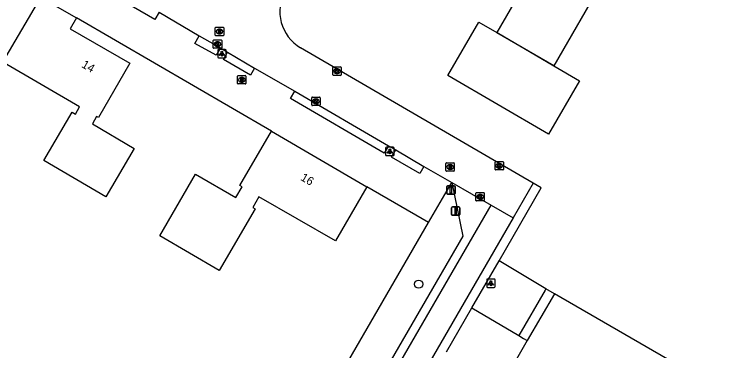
# Model space of a CAD drawing. Extents: x 156502 to 159074, y 384229 to 386094.
# Drawn here: x 157152.4 to 157237.7, y 385787.5 to 385827.5 of the extents above; entities that cross this region are included whole.
import ezdxf

# ---------------------------------------------------------------- set-up
doc = ezdxf.new("R2010")
doc.units = 0
for name, color, linetype in [('IMGEO_Afsluitpaal', 7, 'Continuous'), ('IMGEO_Berm_groen', 7, 'Continuous'), ('IMGEO_Boom', 7, 'Continuous'), ('IMGEO_Grasland_overig', 7, 'Continuous'), ('IMGEO_Groenvoorziening', 7, 'Continuous'), ('IMGEO_Hek', 7, 'Continuous'), ('IMGEO_Kolk', 7, 'Continuous'), ('IMGEO_Lichtpunt', 7, 'Continuous'), ('IMGEO_Pand', 7, 'Continuous'), ('IMGEO_Pand_nummerreeks', 7, 'Continuous'), ('IMGEO_Pand_vergunning_verleend', 7, 'Continuous'), ('IMGEO_Rijbaan_lokaal_gesloten', 7, 'Continuous'), ('IMGEO_Rijbaan_lokaal_halfverhard', 7, 'Continuous'), ('IMGEO_Rijbaan_lokaal_open', 7, 'Continuous'), ('IMGEO_Rioolput', 7, 'Continuous'), ('IMGEO_Voetpad_open', 7, 'Continuous')]:
    doc.layers.add(name, color=color, linetype=linetype)

msp = doc.modelspace()

# ---------------------------------------------------------------- linework, layer by layer
at = {"layer": 'IMGEO_Afsluitpaal'}
for p, q in [((157203.9, 385806.17), (157203.9, 385806.97)), ((157203.9, 385806.97), (157203.9, 385806.17)), ((157204, 385807.07), (157204.79, 385807.07)), ((157204.79, 385807.07), (157204, 385807.07)), ((157204.89, 385806.97), (157204.89, 385806.17)), ((157204.89, 385806.17), (157204.89, 385806.97)), ((157204.79, 385806.07), (157204, 385806.07)), ((157204, 385806.07), (157204.79, 385806.07)), ((157204.466, 385803.659), (157204.466, 385804.459)), ((157204.466, 385804.459), (157204.466, 385803.659)), ((157204.566, 385804.559), (157205.356, 385804.559)), ((157205.356, 385804.559), (157204.566, 385804.559)), ((157205.456, 385804.459), (157205.456, 385803.659)), ((157205.456, 385803.659), (157205.456, 385804.459)), ((157205.356, 385803.559), (157204.566, 385803.559)), ((157204.566, 385803.559), (157205.356, 385803.559))]:
    msp.add_line(p, q, dxfattribs=at)
for points in [[(157204.32, 385806.945), (157204.47, 385806.945), (157204.47, 385806.195), (157204.32, 385806.195), (157204.32, 385806.945)], [(157204.886, 385804.434), (157205.036, 385804.434), (157205.036, 385803.684), (157204.886, 385803.684), (157204.886, 385804.434)]]:
    msp.add_lwpolyline(points, dxfattribs=at)
for centre, start, end in [((157204, 385806.97), 90, 180), ((157204, 385806.97), 90, 180), ((157204.79, 385806.97), 0, 90), ((157204.79, 385806.97), 360, 90), ((157204, 385806.17), 180, 270), ((157204, 385806.17), 180, 270), ((157204.79, 385806.17), 270, 0), ((157204.79, 385806.17), 270, 0), ((157204.566, 385804.459), 90, 180), ((157204.566, 385804.459), 90, 180), ((157205.356, 385804.459), 0, 90), ((157205.356, 385804.459), 360, 90), ((157204.566, 385803.659), 180, 270), ((157204.566, 385803.659), 180, 270), ((157205.356, 385803.659), 270, 0), ((157205.356, 385803.659), 270, 0)]:
    msp.add_arc(centre, 0.1, start, end, dxfattribs=at)
at = {"layer": 'IMGEO_Berm_groen'}
msp.add_lwpolyline([(157149.855, 385730.69), (157157.489, 385726.3), (157201.732, 385802.693)], dxfattribs=at)
at = {"layer": 'IMGEO_Boom'}
msp.add_circle((157200.566, 385795.368), 0.489, dxfattribs=at)
at = {"layer": 'IMGEO_Grasland_overig'}
for points in [[(157215.692, 385794.809), (157210.12, 385798.131)], [(157216.71, 385794.202), (157215.692, 385794.809)], [(157246.925, 385776.791), (157216.71, 385794.202)]]:
    msp.add_lwpolyline(points, dxfattribs=at)
at = {"layer": 'IMGEO_Groenvoorziening'}
for points in [[(157215.692, 385794.809), (157215.606, 385794.649), (157212.477, 385789.254)], [(157216.71, 385794.202), (157213.481, 385788.661)]]:
    msp.add_lwpolyline(points, dxfattribs=at)
at = {"layer": 'IMGEO_Hek'}
for points in [[(157183.031, 385813.57), (157159.85, 385827.054)], [(157201.732, 385802.693), (157194.383, 385806.952)], [(157149.855, 385730.69), (157157.489, 385726.3), (157201.732, 385802.693)]]:
    msp.add_lwpolyline(points, dxfattribs=at)
at = {"layer": 'IMGEO_Kolk'}
for p, q in [((157176.113, 385823.494), (157176.113, 385824.346)), ((157176.188, 385824.42), (157177.04, 385824.42)), ((157177.114, 385824.346), (157177.114, 385823.494)), ((157176.624, 385823.64), (157176.599, 385823.64)), ((157176.601, 385824.2), (157176.626, 385824.2)), ((157177.04, 385823.42), (157176.188, 385823.42)), ((157190.341, 385820.279), (157190.341, 385821.131)), ((157190.416, 385821.205), (157191.268, 385821.205)), ((157190.829, 385820.985), (157190.854, 385820.985)), ((157191.342, 385821.131), (157191.342, 385820.279)), ((157191.268, 385820.205), (157190.416, 385820.205)), ((157190.852, 385820.425), (157190.827, 385820.425)), ((157187.831, 385816.688), (157187.831, 385817.54)), ((157187.906, 385817.614), (157188.758, 385817.614)), ((157188.832, 385817.54), (157188.832, 385816.688)), ((157188.342, 385816.834), (157188.317, 385816.834)), ((157188.319, 385817.394), (157188.344, 385817.394)), ((157188.758, 385816.614), (157187.906, 385816.614)), ((157209.647, 385809.023), (157209.647, 385809.875)), ((157209.722, 385809.949), (157210.574, 385809.949)), ((157210.648, 385809.875), (157210.648, 385809.023)), ((157210.158, 385809.169), (157210.133, 385809.169)), ((157210.135, 385809.729), (157210.16, 385809.729)), ((157210.574, 385808.949), (157209.722, 385808.949)), ((157207.37, 385805.338), (157207.37, 385806.19)), ((157207.445, 385806.264), (157208.297, 385806.264)), ((157207.858, 385806.044), (157207.883, 385806.044)), ((157208.371, 385806.19), (157208.371, 385805.338)), ((157208.297, 385805.264), (157207.445, 385805.264)), ((157207.881, 385805.484), (157207.856, 385805.484))]:
    msp.add_line(p, q, dxfattribs=at)
for points in [[(157176.113, 385823.494), (157176.113, 385824.346)], [(157176.188, 385824.42), (157177.04, 385824.42)], [(157177.114, 385824.346), (157177.114, 385823.494)], [(157176.434, 385824.12), (157176.557, 385824.12), (157176.557, 385823.969), (157176.687, 385824.12), (157176.851, 385824.12), (157176.705, 385823.969), (157176.858, 385823.72), (157176.706, 385823.72), (157176.621, 385823.884), (157176.557, 385823.817), (157176.557, 385823.72), (157176.434, 385823.72), (157176.434, 385824.12)], [(157177.04, 385823.42), (157176.188, 385823.42)], [(157190.341, 385820.279), (157190.341, 385821.131)], [(157190.416, 385821.205), (157191.268, 385821.205)], [(157190.662, 385820.905), (157190.785, 385820.905), (157190.785, 385820.754), (157190.915, 385820.905), (157191.079, 385820.905), (157190.933, 385820.754), (157191.086, 385820.505), (157190.934, 385820.505), (157190.849, 385820.669), (157190.785, 385820.602), (157190.785, 385820.505), (157190.662, 385820.505), (157190.662, 385820.905)], [(157191.342, 385821.131), (157191.342, 385820.279)], [(157191.268, 385820.205), (157190.416, 385820.205)], [(157187.831, 385816.688), (157187.831, 385817.54)], [(157187.906, 385817.614), (157188.758, 385817.614)], [(157188.832, 385817.54), (157188.832, 385816.688)], [(157188.152, 385817.314), (157188.275, 385817.314), (157188.275, 385817.163), (157188.405, 385817.314), (157188.569, 385817.314), (157188.423, 385817.163), (157188.576, 385816.914), (157188.424, 385816.914), (157188.339, 385817.078), (157188.275, 385817.011), (157188.275, 385816.914), (157188.152, 385816.914), (157188.152, 385817.314)], [(157188.758, 385816.614), (157187.906, 385816.614)], [(157209.647, 385809.023), (157209.647, 385809.875)], [(157209.722, 385809.949), (157210.574, 385809.949)], [(157210.648, 385809.875), (157210.648, 385809.023)], [(157209.968, 385809.649), (157210.091, 385809.649), (157210.091, 385809.498), (157210.221, 385809.649), (157210.385, 385809.649), (157210.239, 385809.498), (157210.392, 385809.249), (157210.24, 385809.249), (157210.155, 385809.413), (157210.091, 385809.346), (157210.091, 385809.249), (157209.968, 385809.249), (157209.968, 385809.649)], [(157210.574, 385808.949), (157209.722, 385808.949)], [(157207.37, 385805.338), (157207.37, 385806.19)], [(157207.445, 385806.264), (157208.297, 385806.264)], [(157207.691, 385805.964), (157207.814, 385805.964), (157207.814, 385805.813), (157207.944, 385805.964), (157208.108, 385805.964), (157207.962, 385805.813), (157208.115, 385805.564), (157207.963, 385805.564), (157207.878, 385805.728), (157207.814, 385805.661), (157207.814, 385805.564), (157207.691, 385805.564), (157207.691, 385805.964)], [(157208.371, 385806.19), (157208.371, 385805.338)], [(157208.297, 385805.264), (157207.445, 385805.264)]]:
    msp.add_lwpolyline(points, dxfattribs=at)
for centre, start, end in [((157176.19, 385824.344), 91.55205, 178.44795), ((157176.19, 385824.344), 91.55205, 178.44795), ((157177.038, 385824.344), 1.55205, 88.44795), ((157177.038, 385824.344), 1.55205, 88.44795), ((157176.19, 385823.496), 181.55205, 268.44795), ((157176.19, 385823.496), 181.55205, 268.44795), ((157177.038, 385823.496), 271.55205, 358.44795), ((157177.038, 385823.496), 271.55205, 358.44795), ((157190.418, 385821.129), 91.55205, 178.44795), ((157190.418, 385821.129), 91.55205, 178.44795), ((157191.266, 385821.129), 1.55205, 88.44795), ((157191.266, 385821.129), 1.55205, 88.44795), ((157190.418, 385820.281), 181.55205, 268.44795), ((157190.418, 385820.281), 181.55205, 268.44795), ((157191.266, 385820.281), 271.55205, 358.44795), ((157191.266, 385820.281), 271.55205, 358.44795), ((157187.908, 385817.538), 91.55205, 178.44795), ((157187.908, 385817.538), 91.55205, 178.44795), ((157188.756, 385817.538), 1.55205, 88.44795), ((157188.756, 385817.538), 1.55205, 88.44795), ((157187.908, 385816.69), 181.55205, 268.44795), ((157187.908, 385816.69), 181.55205, 268.44795), ((157188.756, 385816.69), 271.55205, 358.44795), ((157188.756, 385816.69), 271.55205, 358.44795), ((157209.724, 385809.873), 91.55205, 178.44795), ((157209.724, 385809.873), 91.55205, 178.44795), ((157210.572, 385809.873), 1.55205, 88.44795), ((157210.572, 385809.873), 1.55205, 88.44795), ((157209.724, 385809.025), 181.55205, 268.44795), ((157209.724, 385809.025), 181.55205, 268.44795), ((157210.572, 385809.025), 271.55205, 358.44795), ((157210.572, 385809.025), 271.55205, 358.44795), ((157207.447, 385806.188), 91.55205, 178.44795), ((157207.447, 385806.188), 91.55205, 178.44795), ((157208.295, 385806.188), 1.55205, 88.44795), ((157208.295, 385806.188), 1.55205, 88.44795), ((157207.447, 385805.34), 181.55205, 268.44795), ((157207.447, 385805.34), 181.55205, 268.44795), ((157208.295, 385805.34), 271.55205, 358.44795), ((157208.295, 385805.34), 271.55205, 358.44795)]:
    msp.add_arc(centre, 0.0765, start, end, dxfattribs=at)
for centre, major_axis, ratio, start_param, end_param in [((157176.6, 385823.92), (-0.387, 0.002), 0.722429, 4.712389, 7.853982), ((157176.625, 385823.92), (-0.39, 0.002), 0.717154, 1.570796, 4.712389), ((157190.828, 385820.705), (-0.387, 0.002), 0.722429, 4.712389, 7.853982), ((157190.853, 385820.705), (-0.39, 0.002), 0.717154, 1.570796, 4.712389), ((157188.318, 385817.114), (-0.387, 0.002), 0.722429, 4.712389, 7.853982), ((157188.343, 385817.114), (-0.39, 0.002), 0.717154, 1.570796, 4.712389), ((157210.134, 385809.449), (-0.387, 0.002), 0.722429, 4.712389, 7.853982), ((157210.159, 385809.449), (-0.39, 0.002), 0.717154, 1.570796, 4.712389), ((157207.857, 385805.764), (-0.387, 0.002), 0.722429, 4.712389, 7.853982), ((157207.882, 385805.764), (-0.39, 0.002), 0.717154, 1.570796, 4.712389)]:
    msp.add_ellipse(centre, major_axis=major_axis, ratio=ratio, start_param=start_param, end_param=end_param, dxfattribs=at)
at = {"layer": 'IMGEO_Lichtpunt'}
for p, q in [((157176.644, 385823.182), (157176.644, 385822.375)), ((157176.644, 385823.182), (157176.644, 385822.375)), ((157177.546, 385823.277), (157176.738, 385823.277)), ((157177.546, 385823.277), (157176.738, 385823.277)), ((157177.64, 385822.375), (157177.64, 385823.182)), ((157177.64, 385822.375), (157177.64, 385823.182)), ((157176.738, 385822.281), (157177.546, 385822.281)), ((157176.738, 385822.281), (157177.546, 385822.281)), ((157196.63, 385811.564), (157196.63, 385810.757)), ((157196.63, 385811.564), (157196.63, 385810.757)), ((157197.532, 385811.659), (157196.724, 385811.659)), ((157197.532, 385811.659), (157196.724, 385811.659)), ((157197.626, 385810.757), (157197.626, 385811.564)), ((157197.626, 385810.757), (157197.626, 385811.564)), ((157196.724, 385810.663), (157197.532, 385810.663)), ((157196.724, 385810.663), (157197.532, 385810.663)), ((157208.654, 385795.885), (157208.654, 385795.078)), ((157208.654, 385795.885), (157208.654, 385795.078)), ((157209.556, 385795.98), (157208.748, 385795.98)), ((157209.556, 385795.98), (157208.748, 385795.98)), ((157209.65, 385795.078), (157209.65, 385795.885)), ((157209.65, 385795.078), (157209.65, 385795.885)), ((157208.748, 385794.984), (157209.556, 385794.984)), ((157208.748, 385794.984), (157209.556, 385794.984))]:
    msp.add_line(p, q, dxfattribs=at)
for points in [[(157177.018, 385822.846), (157177.057, 385822.818), (157176.869, 385822.556), (157176.831, 385822.583), (157177.018, 385822.846)], [(157177.12, 385822.798), (157177.167, 385822.798), (157177.167, 385822.476), (157177.12, 385822.476), (157177.12, 385822.798)], [(157177.23, 385822.818), (157177.268, 385822.845), (157177.455, 385822.583), (157177.416, 385822.555), (157177.23, 385822.818)], [(157197.004, 385811.228), (157197.043, 385811.2), (157196.855, 385810.938), (157196.817, 385810.965), (157197.004, 385811.228)], [(157197.106, 385811.18), (157197.153, 385811.18), (157197.153, 385810.858), (157197.106, 385810.858), (157197.106, 385811.18)], [(157197.216, 385811.2), (157197.254, 385811.227), (157197.441, 385810.965), (157197.402, 385810.937), (157197.216, 385811.2)], [(157209.028, 385795.549), (157209.067, 385795.521), (157208.879, 385795.259), (157208.841, 385795.286), (157209.028, 385795.549)], [(157209.13, 385795.501), (157209.177, 385795.501), (157209.177, 385795.179), (157209.13, 385795.179), (157209.13, 385795.501)], [(157209.24, 385795.521), (157209.278, 385795.548), (157209.465, 385795.286), (157209.426, 385795.258), (157209.24, 385795.521)]]:
    msp.add_lwpolyline(points, dxfattribs=at)
for centre in [(157177.143, 385822.98), (157197.129, 385811.362), (157209.153, 385795.683)]:
    msp.add_circle(centre, 0.0994, dxfattribs=at)
for centre, start, end in [((157176.738, 385823.182), 90, 180), ((157176.738, 385823.182), 90, 180), ((157177.546, 385823.182), 0, 90), ((157177.546, 385823.182), 0, 90), ((157176.738, 385822.375), 180, 270), ((157176.738, 385822.375), 180, 270), ((157177.546, 385822.375), 270, 0), ((157177.546, 385822.375), 270, 360), ((157196.724, 385811.564), 90, 180), ((157196.724, 385811.564), 90, 180), ((157197.532, 385811.564), 0, 90), ((157197.532, 385811.564), 0, 90), ((157196.724, 385810.757), 180, 270), ((157196.724, 385810.757), 180, 270), ((157197.532, 385810.757), 270, 0), ((157197.532, 385810.757), 270, 360), ((157208.748, 385795.885), 90, 180), ((157208.748, 385795.885), 90, 180), ((157209.556, 385795.885), 0, 90), ((157209.556, 385795.885), 0, 90), ((157208.748, 385795.078), 180, 270), ((157208.748, 385795.078), 180, 270), ((157209.556, 385795.078), 270, 0), ((157209.556, 385795.078), 270, 360)]:
    msp.add_arc(centre, 0.0946, start, end, dxfattribs=at)
at = {"layer": 'IMGEO_Pand'}
for points in [[(157159.85, 385827.054), (157159.093, 385825.747), (157166.175, 385821.643), (157162.465, 385815.184), (157162.231, 385815.319), (157161.733, 385814.451), (157166.702, 385811.491), (157163.329, 385805.74), (157155.962, 385810.061), (157159.324, 385815.821), (157159.704, 385815.599), (157160.195, 385816.468), (157151.075, 385821.767), (157155.595, 385829.52)], [(157155.595, 385829.52), (157159.85, 385827.054)], [(157194.383, 385806.952), (157190.645, 385800.522), (157181.547, 385805.765), (157180.811, 385804.505), (157181.113, 385804.328), (157176.827, 385796.988), (157169.771, 385801.108), (157174.018, 385808.44), (157178.814, 385805.661), (157179.553, 385806.928), (157179.259, 385807.099), (157183.031, 385813.57)], [(157183.031, 385813.57), (157194.383, 385806.952)]]:
    msp.add_lwpolyline(points, dxfattribs=at)
at = {"layer": 'IMGEO_Pand_vergunning_verleend'}
for points in [[(157209.892, 385825.287), (157215.806, 385835.51), (157222.569, 385831.597), (157216.642, 385821.353)], [(157216.642, 385821.353), (157219.712, 385819.564), (157216.003, 385813.2), (157204.018, 385820.184), (157207.727, 385826.548), (157209.872, 385825.298), (157209.892, 385825.287)], [(157216.642, 385821.353), (157209.879, 385825.265), (157209.892, 385825.287)], [(157209.892, 385825.287), (157216.642, 385821.353)]]:
    msp.add_lwpolyline(points, dxfattribs=at)
at = {"layer": 'IMGEO_Rijbaan_lokaal_gesloten'}
for points in [[(157163.025, 385725.068), (157209.184, 385804.754)], [(157209.184, 385804.754), (157211.808, 385803.246)], [(157211.808, 385803.246), (157164.84, 385722.131)]]:
    msp.add_lwpolyline(points, dxfattribs=at)
at = {"layer": 'IMGEO_Rijbaan_lokaal_halfverhard'}
msp.add_lwpolyline([(157204.517, 385807.457), (157205.798, 385801.093), (157162.191, 385725.838)], dxfattribs=at)
at = {"layer": 'IMGEO_Rijbaan_lokaal_open'}
for points in [[(157169.662, 385827.706), (157174.449, 385824.915)], [(157174.449, 385824.915), (157176.957, 385823.481)], [(157176.957, 385823.481), (157177.826, 385822.969)], [(157214.196, 385807.371), (157186.511, 385823.495)], [(157177.826, 385822.969), (157181.039, 385821.079)], [(157181.039, 385821.079), (157185.809, 385818.305)], [(157185.809, 385818.305), (157196.965, 385811.84)], [(157196.965, 385811.84), (157197.832, 385811.333)], [(157197.832, 385811.333), (157201.192, 385809.384)], [(157201.192, 385809.384), (157204.517, 385807.457)], [(157204.517, 385807.457), (157209.184, 385804.754)], [(157210.12, 385798.131), (157215.153, 385806.818), (157214.196, 385807.371)], [(157214.196, 385807.371), (157211.808, 385803.246)], [(157206.888, 385792.553), (157210.12, 385798.131)], [(157203.866, 385787.336), (157206.888, 385792.553)], [(157206.888, 385792.553), (157212.477, 385789.254)], [(157213.481, 385788.661), (157210.483, 385783.472)], [(157212.477, 385789.254), (157213.054, 385788.913), (157213.481, 385788.661)]]:
    msp.add_lwpolyline(points, dxfattribs=at)
msp.add_arc((157189.041, 385827.813), 5.005, 150.73374, 239.63455, dxfattribs=at)
at = {"layer": 'IMGEO_Rioolput'}
for p, q in [((157176.353, 385824.991), (157176.353, 385825.843)), ((157176.428, 385825.917), (157177.28, 385825.917)), ((157176.841, 385825.697), (157176.866, 385825.697)), ((157177.354, 385825.843), (157177.354, 385824.991)), ((157177.28, 385824.917), (157176.428, 385824.917)), ((157176.864, 385825.137), (157176.839, 385825.137)), ((157179.003, 385819.252), (157179.003, 385820.104)), ((157179.078, 385820.178), (157179.93, 385820.178)), ((157180.004, 385820.104), (157180.004, 385819.252)), ((157179.514, 385819.398), (157179.489, 385819.398)), ((157179.491, 385819.958), (157179.516, 385819.958)), ((157179.93, 385819.178), (157179.078, 385819.178)), ((157203.802, 385808.879), (157203.802, 385809.731)), ((157203.877, 385809.805), (157204.729, 385809.805)), ((157204.313, 385809.025), (157204.288, 385809.025)), ((157204.29, 385809.585), (157204.315, 385809.585)), ((157204.803, 385809.731), (157204.803, 385808.879)), ((157204.729, 385808.805), (157203.877, 385808.805))]:
    msp.add_line(p, q, dxfattribs=at)
for points in [[(157176.353, 385824.991), (157176.353, 385825.843)], [(157176.428, 385825.917), (157177.28, 385825.917)], [(157176.942, 385825.615), (157176.69, 385825.617), (157176.69, 385825.217)], [(157176.69, 385825.217), (157176.814, 385825.217), (157176.814, 385825.379), (157176.825, 385825.379)], [(157176.868, 385825.536), (157176.814, 385825.536), (157176.814, 385825.455)], [(157176.814, 385825.455), (157176.866, 385825.455)], [(157176.872, 385825.35), (157176.943, 385825.217), (157177.083, 385825.217), (157177.018, 385825.343)], [(157177.354, 385825.843), (157177.354, 385824.991)], [(157177.28, 385824.917), (157176.428, 385824.917)], [(157179.003, 385819.252), (157179.003, 385820.104)], [(157179.078, 385820.178), (157179.93, 385820.178)], [(157180.004, 385820.104), (157180.004, 385819.252)], [(157179.592, 385819.876), (157179.34, 385819.878), (157179.34, 385819.478)], [(157179.34, 385819.478), (157179.464, 385819.478), (157179.464, 385819.64), (157179.475, 385819.64)], [(157179.518, 385819.797), (157179.464, 385819.797), (157179.464, 385819.716)], [(157179.464, 385819.716), (157179.516, 385819.716)], [(157179.522, 385819.611), (157179.593, 385819.478), (157179.733, 385819.478), (157179.668, 385819.604)], [(157179.93, 385819.178), (157179.078, 385819.178)], [(157203.802, 385808.879), (157203.802, 385809.731)], [(157203.877, 385809.805), (157204.729, 385809.805)], [(157204.391, 385809.503), (157204.139, 385809.505), (157204.139, 385809.105)], [(157204.139, 385809.105), (157204.263, 385809.105), (157204.263, 385809.267), (157204.274, 385809.267)], [(157204.317, 385809.424), (157204.263, 385809.424), (157204.263, 385809.343)], [(157204.263, 385809.343), (157204.315, 385809.343)], [(157204.321, 385809.238), (157204.392, 385809.105), (157204.532, 385809.105), (157204.467, 385809.231)], [(157204.803, 385809.731), (157204.803, 385808.879)], [(157204.729, 385808.805), (157203.877, 385808.805)]]:
    msp.add_lwpolyline(points, dxfattribs=at)
for centre, radius, start, end in [((157176.43, 385825.841), 0.0765, 91.55205, 178.44795), ((157176.43, 385825.841), 0.0765, 91.55205, 178.44795), ((157176.824, 385825.326), 0.0533, 26.02933, 88.69889), ((157176.85, 385825.644), 0.19, 274.7715, 282.96867), ((157176.874, 385825.44), 0.0964, 77.00612, 93.18647), ((157176.888, 385825.497), 0.0378, 276.66336, 79.67722), ((157176.941, 385825.505), 0.109, 350.36119, 89.41601), ((157176.939, 385825.505), 0.112, 277.58423, 350.98172), ((157176.923, 385825.29), 0.108, 29.51342, 73.79051), ((157177.278, 385825.841), 0.0765, 1.55205, 88.44795), ((157177.278, 385825.841), 0.0765, 1.55205, 88.44795), ((157176.43, 385824.993), 0.0765, 181.55205, 268.44795), ((157176.43, 385824.993), 0.0765, 181.55205, 268.44795), ((157177.278, 385824.993), 0.0765, 271.55205, 358.44795), ((157177.278, 385824.993), 0.0765, 271.55205, 358.44795), ((157179.08, 385820.102), 0.0765, 91.55205, 178.44795), ((157179.08, 385820.102), 0.0765, 91.55205, 178.44795), ((157179.928, 385820.102), 0.0765, 1.55205, 88.44795), ((157179.928, 385820.102), 0.0765, 1.55205, 88.44795), ((157179.08, 385819.254), 0.0765, 181.55205, 268.44795), ((157179.08, 385819.254), 0.0765, 181.55205, 268.44795), ((157179.474, 385819.587), 0.0533, 26.02933, 88.69889), ((157179.5, 385819.905), 0.19, 274.7715, 282.96867), ((157179.524, 385819.701), 0.0964, 77.00612, 93.18647), ((157179.538, 385819.758), 0.0378, 276.66336, 79.67722), ((157179.591, 385819.766), 0.109, 350.36119, 89.41601), ((157179.589, 385819.766), 0.112, 277.58423, 350.98172), ((157179.573, 385819.551), 0.108, 29.51342, 73.79051), ((157179.928, 385819.254), 0.0765, 271.55205, 358.44795), ((157179.928, 385819.254), 0.0765, 271.55205, 358.44795), ((157203.879, 385809.729), 0.0765, 91.55205, 178.44795), ((157203.879, 385809.729), 0.0765, 91.55205, 178.44795), ((157204.273, 385809.214), 0.0533, 26.02933, 88.69889), ((157204.299, 385809.532), 0.19, 274.7715, 282.96867), ((157204.323, 385809.328), 0.0964, 77.00612, 93.18647), ((157204.337, 385809.385), 0.0378, 276.66336, 79.67722), ((157204.39, 385809.393), 0.109, 350.36119, 89.41601), ((157204.388, 385809.393), 0.112, 277.58423, 350.98172), ((157204.372, 385809.178), 0.108, 29.51342, 73.79051), ((157204.727, 385809.729), 0.0765, 1.55205, 88.44795), ((157204.727, 385809.729), 0.0765, 1.55205, 88.44795), ((157203.879, 385808.881), 0.0765, 181.55205, 268.44795), ((157203.879, 385808.881), 0.0765, 181.55205, 268.44795), ((157204.727, 385808.881), 0.0765, 271.55205, 358.44795), ((157204.727, 385808.881), 0.0765, 271.55205, 358.44795)]:
    msp.add_arc(centre, radius, start, end, dxfattribs=at)
for centre, major_axis, ratio, start_param, end_param in [((157176.84, 385825.417), (-0.387, 0.002), 0.722429, 4.712389, 7.853982), ((157176.865, 385825.417), (-0.39, 0.002), 0.717154, 1.570796, 4.712389), ((157179.49, 385819.678), (-0.387, 0.002), 0.722429, 4.712389, 7.853982), ((157179.515, 385819.678), (-0.39, 0.002), 0.717154, 1.570796, 4.712389), ((157204.289, 385809.305), (-0.387, 0.002), 0.722429, 4.712389, 7.853982), ((157204.314, 385809.305), (-0.39, 0.002), 0.717154, 1.570796, 4.712389)]:
    msp.add_ellipse(centre, major_axis=major_axis, ratio=ratio, start_param=start_param, end_param=end_param, dxfattribs=at)
at = {"layer": 'IMGEO_Voetpad_open'}
for points in [[(157169.662, 385827.706), (157169.178, 385826.84), (157159.74, 385832.335), (157160.239, 385833.196)], [(157183.031, 385813.57), (157159.85, 385827.054)], [(157176.957, 385823.481), (157176.468, 385822.604), (157173.918, 385823.999), (157174.449, 385824.915)], [(157181.039, 385821.079), (157180.564, 385820.235), (157177.317, 385822.102), (157177.826, 385822.969)], [(157196.965, 385811.84), (157196.454, 385810.969), (157185.313, 385817.465), (157185.809, 385818.305)], [(157201.192, 385809.384), (157200.709, 385808.513), (157197.341, 385810.462), (157197.832, 385811.333)], [(157201.732, 385802.693), (157204.517, 385807.457)], [(157201.732, 385802.693), (157194.383, 385806.952)]]:
    msp.add_lwpolyline(points, dxfattribs=at)

# ---------------------------------------------------------------- texts
at = {"layer": 'IMGEO_Pand_nummerreeks'}
for s, rotation, p in [('14', 329.9055, (157160.356, 385821.224)), ('16', 329.75851, (157186.422, 385807.796))]:
    msp.add_text(s, height=1, rotation=rotation, dxfattribs=at).set_placement(p)

doc.saveas('drawing.dxf')
